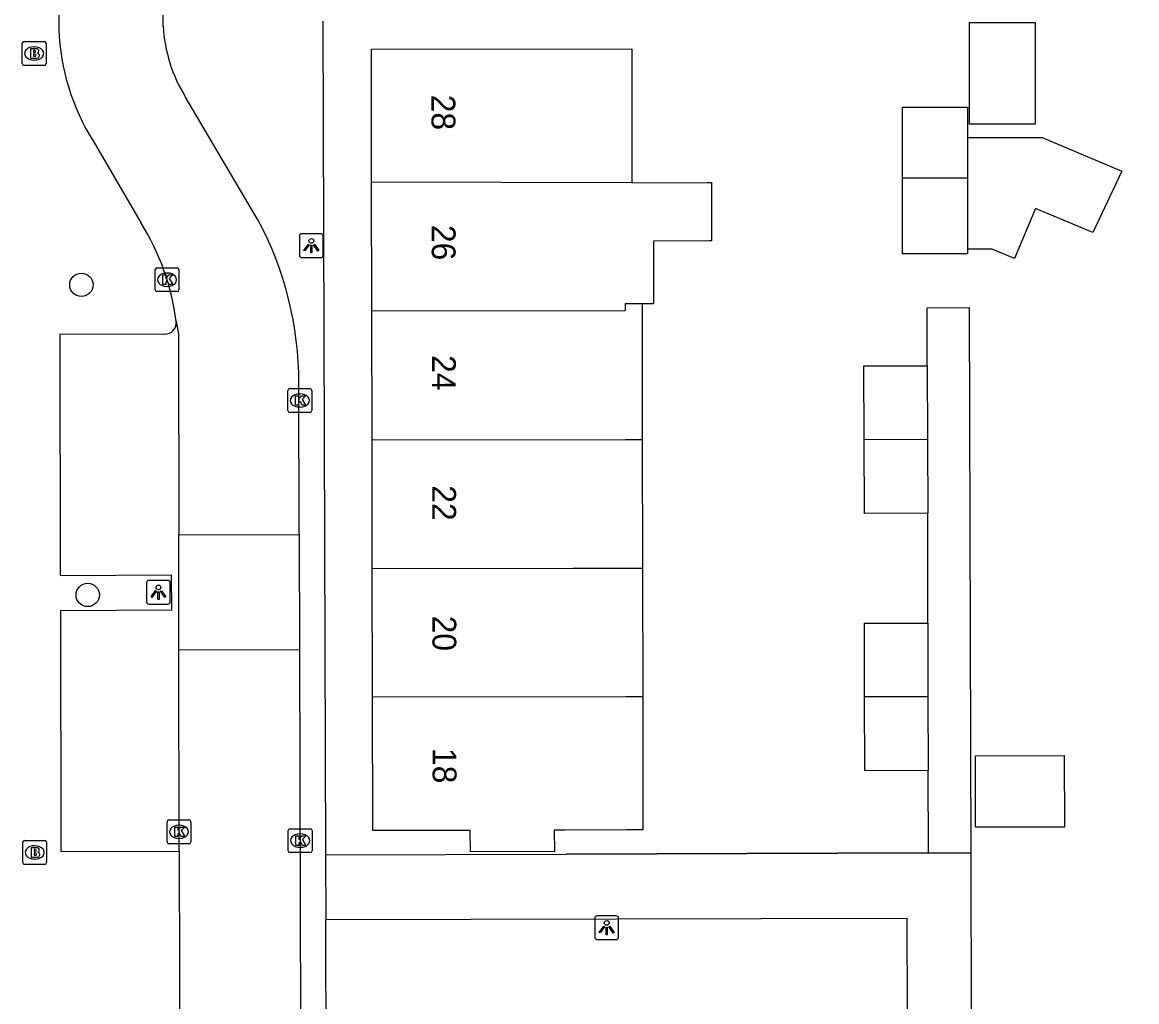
# Model space of a CAD drawing. Extents: x 160457 to 162082, y 388340 to 389736.
# Drawn here: x 160945.33 to 160992.11, y 388549.23 to 388590.34 of the extents above; entities that cross this region are included whole.
import ezdxf

# ---------------------------------------------------------------- set-up
doc = ezdxf.new("R2010")
doc.units = 0
for name, color, linetype in [('IMGEO_Boom', 7, 'Continuous'), ('IMGEO_Brandkraan', 7, 'Continuous'), ('IMGEO_Kolk', 7, 'Continuous'), ('IMGEO_Lichtpunt', 7, 'Continuous'), ('IMGEO_Muur', 7, 'Continuous'), ('IMGEO_Pand', 7, 'Continuous'), ('IMGEO_Pand_nummerreeks', 7, 'Continuous'), ('IMGEO_Rijbaan_lokaal_open', 7, 'Continuous'), ('IMGEO_Voetpad_open', 7, 'Continuous')]:
    doc.layers.add(name, color=color, linetype=linetype)

msp = doc.modelspace()

# ---------------------------------------------------------------- linework, layer by layer
at = {"layer": 'IMGEO_Boom'}
for centre in [(160947.807, 388579.324), (160948.073, 388566.305)]:
    msp.add_circle(centre, 0.489, dxfattribs=at)
at = {"layer": 'IMGEO_Brandkraan'}
for p, q in [((160945.326, 388588.611), (160945.326, 388589.463)), ((160945.401, 388589.537), (160946.253, 388589.537)), ((160945.814, 388589.317), (160945.839, 388589.317)), ((160946.327, 388589.463), (160946.327, 388588.611)), ((160946.253, 388588.537), (160945.401, 388588.537)), ((160945.837, 388588.757), (160945.812, 388588.757)), ((160945.347, 388555.071), (160945.347, 388555.923)), ((160945.422, 388555.997), (160946.274, 388555.997)), ((160945.835, 388555.777), (160945.86, 388555.777)), ((160946.348, 388555.923), (160946.348, 388555.071)), ((160945.858, 388555.217), (160945.833, 388555.217)), ((160946.274, 388554.997), (160945.422, 388554.997))]:
    msp.add_line(p, q, dxfattribs=at)
for points in [[(160945.326, 388588.611), (160945.326, 388589.463)], [(160945.401, 388589.537), (160946.253, 388589.537)], [(160946.327, 388589.463), (160946.327, 388588.611)], [(160945.674, 388589.237), (160945.674, 388588.837), (160945.887, 388588.837)], [(160945.905, 388589.237), (160945.674, 388589.237)], [(160945.853, 388589.156), (160945.799, 388589.156), (160945.799, 388589.08)], [(160945.799, 388589.08), (160945.852, 388589.08)], [(160945.861, 388589.004), (160945.799, 388589.004), (160945.799, 388588.923)], [(160945.799, 388588.923), (160945.861, 388588.923)], [(160946.253, 388588.537), (160945.401, 388588.537)], [(160945.347, 388555.071), (160945.347, 388555.923)], [(160945.422, 388555.997), (160946.274, 388555.997)], [(160945.695, 388555.697), (160945.695, 388555.297), (160945.908, 388555.297)], [(160945.926, 388555.697), (160945.695, 388555.697)], [(160945.874, 388555.616), (160945.82, 388555.616), (160945.82, 388555.54)], [(160946.348, 388555.923), (160946.348, 388555.071)], [(160945.82, 388555.54), (160945.873, 388555.54)], [(160945.882, 388555.464), (160945.82, 388555.464), (160945.82, 388555.383)], [(160945.82, 388555.383), (160945.882, 388555.383)], [(160946.274, 388554.997), (160945.422, 388554.997)]]:
    msp.add_lwpolyline(points, dxfattribs=at)
for centre, radius, start, end in [((160945.403, 388589.461), 0.0765, 91.552, 178.448), ((160945.403, 388589.461), 0.0765, 91.552, 178.448), ((160946.251, 388589.461), 0.0765, 1.552, 88.448), ((160946.251, 388589.461), 0.0765, 1.552, 88.448), ((160945.854, 388589.118), 0.0379, 267.8285, 90.9355), ((160945.862, 388588.963), 0.0404, 269.8759, 90.5077), ((160945.893, 388589.088), 0.251, 268.6676, 293.5347), ((160945.909, 388589.092), 0.145, 59.4692, 91.5367), ((160945.934, 388589.139), 0.0922, 285.5137, 58.1501), ((160945.939, 388588.947), 0.105, 301.3115, 78.989), ((160945.403, 388588.613), 0.0765, 181.552, 268.448), ((160945.403, 388588.613), 0.0765, 181.552, 268.448), ((160946.251, 388588.613), 0.0765, 271.552, 358.448), ((160946.251, 388588.613), 0.0765, 271.552, 358.448), ((160945.424, 388555.921), 0.0765, 91.552, 178.448), ((160945.424, 388555.921), 0.0765, 91.552, 178.448), ((160945.875, 388555.578), 0.0379, 267.8285, 90.9355), ((160945.93, 388555.552), 0.145, 59.4692, 91.5367), ((160945.955, 388555.599), 0.0922, 285.5137, 58.1501), ((160946.272, 388555.921), 0.0765, 1.552, 88.448), ((160946.272, 388555.921), 0.0765, 1.552, 88.448), ((160945.883, 388555.423), 0.0404, 269.8759, 90.5077), ((160945.914, 388555.548), 0.251, 268.6676, 293.5347), ((160945.96, 388555.407), 0.105, 301.3115, 78.989), ((160945.424, 388555.073), 0.0765, 181.552, 268.448), ((160945.424, 388555.073), 0.0765, 181.552, 268.448), ((160946.272, 388555.073), 0.0765, 271.552, 358.448), ((160946.272, 388555.073), 0.0765, 271.552, 358.448)]:
    msp.add_arc(centre, radius, start, end, dxfattribs=at)
for centre, major_axis, ratio, start_param, end_param in [((160945.813, 388589.037), (-0.387, 0.002), 0.722429, 4.712389, 7.853982), ((160945.838, 388589.037), (-0.39, 0.002), 0.717154, 1.570796, 4.712389), ((160945.834, 388555.497), (-0.387, 0.002), 0.722429, 4.712389, 7.853982), ((160945.859, 388555.497), (-0.39, 0.002), 0.717154, 1.570796, 4.712389)]:
    msp.add_ellipse(centre, major_axis=major_axis, ratio=ratio, start_param=start_param, end_param=end_param, dxfattribs=at)
at = {"layer": 'IMGEO_Kolk'}
for p, q in [((160950.903, 388579.112), (160950.903, 388579.964)), ((160950.978, 388580.038), (160951.83, 388580.038)), ((160951.904, 388579.964), (160951.904, 388579.112)), ((160951.391, 388579.818), (160951.416, 388579.818)), ((160951.83, 388579.038), (160950.978, 388579.038)), ((160951.414, 388579.258), (160951.389, 388579.258)), ((160956.477, 388574.042), (160956.477, 388574.894)), ((160956.552, 388574.968), (160957.404, 388574.968)), ((160956.965, 388574.748), (160956.99, 388574.748)), ((160957.478, 388574.894), (160957.478, 388574.042)), ((160957.404, 388573.968), (160956.552, 388573.968)), ((160956.988, 388574.188), (160956.963, 388574.188)), ((160951.406, 388555.936), (160951.406, 388556.788)), ((160951.481, 388556.862), (160952.333, 388556.862)), ((160951.894, 388556.642), (160951.919, 388556.642)), ((160952.407, 388556.788), (160952.407, 388555.936)), ((160951.917, 388556.082), (160951.892, 388556.082)), ((160956.491, 388555.567), (160956.491, 388556.419)), ((160956.566, 388556.493), (160957.418, 388556.493)), ((160956.979, 388556.273), (160957.004, 388556.273)), ((160957.492, 388556.419), (160957.492, 388555.567)), ((160952.333, 388555.862), (160951.481, 388555.862)), ((160957.002, 388555.713), (160956.977, 388555.713)), ((160957.418, 388555.493), (160956.566, 388555.493))]:
    msp.add_line(p, q, dxfattribs=at)
for points in [[(160950.903, 388579.112), (160950.903, 388579.964)], [(160950.978, 388580.038), (160951.83, 388580.038)], [(160951.904, 388579.964), (160951.904, 388579.112)], [(160951.224, 388579.738), (160951.347, 388579.738), (160951.347, 388579.587), (160951.477, 388579.738), (160951.641, 388579.738), (160951.495, 388579.587), (160951.648, 388579.338), (160951.496, 388579.338), (160951.411, 388579.502), (160951.347, 388579.435), (160951.347, 388579.338), (160951.224, 388579.338), (160951.224, 388579.738)], [(160951.83, 388579.038), (160950.978, 388579.038)], [(160956.477, 388574.042), (160956.477, 388574.894)], [(160956.552, 388574.968), (160957.404, 388574.968)], [(160957.478, 388574.894), (160957.478, 388574.042)], [(160956.798, 388574.668), (160956.921, 388574.668), (160956.921, 388574.517), (160957.051, 388574.668), (160957.215, 388574.668), (160957.069, 388574.517), (160957.222, 388574.268), (160957.07, 388574.268), (160956.985, 388574.432), (160956.921, 388574.365), (160956.921, 388574.268), (160956.798, 388574.268), (160956.798, 388574.668)], [(160957.404, 388573.968), (160956.552, 388573.968)], [(160951.406, 388555.936), (160951.406, 388556.788)], [(160951.481, 388556.862), (160952.333, 388556.862)], [(160951.727, 388556.562), (160951.85, 388556.562), (160951.85, 388556.411), (160951.98, 388556.562), (160952.144, 388556.562), (160951.998, 388556.411), (160952.151, 388556.162), (160951.999, 388556.162), (160951.914, 388556.326), (160951.85, 388556.259), (160951.85, 388556.162), (160951.727, 388556.162), (160951.727, 388556.562)], [(160952.407, 388556.788), (160952.407, 388555.936)], [(160956.491, 388555.567), (160956.491, 388556.419)], [(160956.566, 388556.493), (160957.418, 388556.493)], [(160956.812, 388556.193), (160956.935, 388556.193), (160956.935, 388556.042), (160957.065, 388556.193), (160957.229, 388556.193), (160957.083, 388556.042), (160957.236, 388555.793), (160957.084, 388555.793), (160956.999, 388555.957), (160956.935, 388555.89), (160956.935, 388555.793), (160956.812, 388555.793), (160956.812, 388556.193)], [(160957.492, 388556.419), (160957.492, 388555.567)], [(160952.333, 388555.862), (160951.481, 388555.862)], [(160957.418, 388555.493), (160956.566, 388555.493)]]:
    msp.add_lwpolyline(points, dxfattribs=at)
for centre, start, end in [((160950.98, 388579.962), 91.552, 178.448), ((160950.98, 388579.962), 91.552, 178.448), ((160951.828, 388579.962), 1.552, 88.448), ((160951.828, 388579.962), 1.552, 88.448), ((160950.98, 388579.114), 181.552, 268.448), ((160950.98, 388579.114), 181.552, 268.448), ((160951.828, 388579.114), 271.552, 358.448), ((160951.828, 388579.114), 271.552, 358.448), ((160956.554, 388574.892), 91.552, 178.448), ((160956.554, 388574.892), 91.552, 178.448), ((160957.402, 388574.892), 1.552, 88.448), ((160957.402, 388574.892), 1.552, 88.448), ((160956.554, 388574.044), 181.552, 268.448), ((160956.554, 388574.044), 181.552, 268.448), ((160957.402, 388574.044), 271.552, 358.448), ((160957.402, 388574.044), 271.552, 358.448), ((160951.483, 388556.786), 91.552, 178.448), ((160951.483, 388556.786), 91.552, 178.448), ((160952.331, 388556.786), 1.552, 88.448), ((160952.331, 388556.786), 1.552, 88.448), ((160956.568, 388556.417), 91.552, 178.448), ((160956.568, 388556.417), 91.552, 178.448), ((160957.416, 388556.417), 1.552, 88.448), ((160957.416, 388556.417), 1.552, 88.448), ((160951.483, 388555.938), 181.552, 268.448), ((160951.483, 388555.938), 181.552, 268.448), ((160952.331, 388555.938), 271.552, 358.448), ((160952.331, 388555.938), 271.552, 358.448), ((160956.568, 388555.569), 181.552, 268.448), ((160956.568, 388555.569), 181.552, 268.448), ((160957.416, 388555.569), 271.552, 358.448), ((160957.416, 388555.569), 271.552, 358.448)]:
    msp.add_arc(centre, 0.0765, start, end, dxfattribs=at)
for centre, major_axis, ratio, start_param, end_param in [((160951.39, 388579.538), (-0.387, 0.002), 0.722429, 4.712389, 7.853982), ((160951.415, 388579.538), (-0.39, 0.002), 0.717154, 1.570796, 4.712389), ((160956.964, 388574.468), (-0.387, 0.002), 0.722429, 4.712389, 7.853982), ((160956.989, 388574.468), (-0.39, 0.002), 0.717154, 1.570796, 4.712389), ((160951.893, 388556.362), (-0.387, 0.002), 0.722429, 4.712389, 7.853982), ((160951.918, 388556.362), (-0.39, 0.002), 0.717154, 1.570796, 4.712389), ((160956.978, 388555.993), (-0.387, 0.002), 0.722429, 4.712389, 7.853982), ((160957.003, 388555.993), (-0.39, 0.002), 0.717154, 1.570796, 4.712389)]:
    msp.add_ellipse(centre, major_axis=major_axis, ratio=ratio, start_param=start_param, end_param=end_param, dxfattribs=at)
at = {"layer": 'IMGEO_Lichtpunt'}
for p, q in [((160956.963, 388581.371), (160956.963, 388580.564)), ((160956.963, 388581.371), (160956.963, 388580.564)), ((160957.865, 388581.466), (160957.057, 388581.466)), ((160957.865, 388581.466), (160957.057, 388581.466)), ((160957.959, 388580.564), (160957.959, 388581.371)), ((160957.959, 388580.564), (160957.959, 388581.371)), ((160957.057, 388580.47), (160957.865, 388580.47)), ((160957.057, 388580.47), (160957.865, 388580.47)), ((160950.543, 388566.822), (160950.543, 388566.015)), ((160950.543, 388566.822), (160950.543, 388566.015)), ((160951.445, 388566.917), (160950.637, 388566.917)), ((160951.445, 388566.917), (160950.637, 388566.917)), ((160951.539, 388566.015), (160951.539, 388566.822)), ((160951.539, 388566.015), (160951.539, 388566.822)), ((160950.637, 388565.921), (160951.445, 388565.921)), ((160950.637, 388565.921), (160951.445, 388565.921)), ((160970.263, 388552.836), (160969.455, 388552.836)), ((160970.263, 388552.836), (160969.455, 388552.836)), ((160969.361, 388552.741), (160969.361, 388551.934)), ((160969.361, 388552.741), (160969.361, 388551.934)), ((160970.357, 388551.934), (160970.357, 388552.741)), ((160970.357, 388551.934), (160970.357, 388552.741)), ((160969.455, 388551.84), (160970.263, 388551.84)), ((160969.455, 388551.84), (160970.263, 388551.84))]:
    msp.add_line(p, q, dxfattribs=at)
for points in [[(160957.337, 388581.035), (160957.376, 388581.007), (160957.188, 388580.745), (160957.15, 388580.772), (160957.337, 388581.035)], [(160957.439, 388580.987), (160957.486, 388580.987), (160957.486, 388580.665), (160957.439, 388580.665), (160957.439, 388580.987)], [(160957.549, 388581.007), (160957.587, 388581.034), (160957.774, 388580.772), (160957.735, 388580.744), (160957.549, 388581.007)], [(160950.917, 388566.486), (160950.956, 388566.458), (160950.768, 388566.196), (160950.73, 388566.223), (160950.917, 388566.486)], [(160951.019, 388566.438), (160951.066, 388566.438), (160951.066, 388566.116), (160951.019, 388566.116), (160951.019, 388566.438)], [(160951.129, 388566.458), (160951.167, 388566.485), (160951.354, 388566.223), (160951.315, 388566.195), (160951.129, 388566.458)], [(160969.735, 388552.405), (160969.774, 388552.377), (160969.586, 388552.115), (160969.548, 388552.142), (160969.735, 388552.405)], [(160969.837, 388552.357), (160969.884, 388552.357), (160969.884, 388552.035), (160969.837, 388552.035), (160969.837, 388552.357)], [(160969.947, 388552.377), (160969.985, 388552.404), (160970.172, 388552.142), (160970.133, 388552.114), (160969.947, 388552.377)]]:
    msp.add_lwpolyline(points, dxfattribs=at)
for centre in [(160957.462, 388581.169), (160951.042, 388566.62), (160969.86, 388552.539)]:
    msp.add_circle(centre, 0.0994, dxfattribs=at)
for centre, start, end in [((160957.057, 388581.371), 90, 180), ((160957.057, 388581.371), 90, 180), ((160957.865, 388581.371), 0, 90), ((160957.865, 388581.371), 0, 90), ((160957.057, 388580.564), 180, 270), ((160957.057, 388580.564), 180, 270), ((160957.865, 388580.564), 270, 0), ((160957.865, 388580.564), 270, 360), ((160950.637, 388566.822), 90, 180), ((160950.637, 388566.822), 90, 180), ((160951.445, 388566.822), 0, 90), ((160951.445, 388566.822), 0, 90), ((160950.637, 388566.015), 180, 270), ((160950.637, 388566.015), 180, 270), ((160951.445, 388566.015), 270, 0), ((160951.445, 388566.015), 270, 360), ((160969.455, 388552.741), 90, 180), ((160969.455, 388552.741), 90, 180), ((160970.263, 388552.741), 0, 90), ((160970.263, 388552.741), 0, 90), ((160969.455, 388551.934), 180, 270), ((160969.455, 388551.934), 180, 270), ((160970.263, 388551.934), 270, 0), ((160970.263, 388551.934), 270, 360)]:
    msp.add_arc(centre, 0.0946, start, end, dxfattribs=at)
at = {"layer": 'IMGEO_Muur'}
for points in [[(160983.369, 388555.475), (160968.14, 388555.428)], [(160985.147, 388555.481), (160985.162, 388548.37), (161001.342, 388548.405)]]:
    msp.add_lwpolyline(points, dxfattribs=at)
at = {"layer": 'IMGEO_Pand'}
for points in [[(160987.85, 388586.062), (160985.087, 388586.062), (160985.087, 388590.342), (160987.85, 388590.342), (160987.85, 388586.062)], [(160959.991, 388583.627), (160959.981, 388589.211), (160970.911, 388589.231), (160970.921, 388583.612)], [(160982.273, 388583.801), (160982.273, 388586.785), (160985.003, 388586.785), (160985.003, 388585.504)], [(160985.003, 388585.504), (160985.003, 388583.806)], [(160985.003, 388585.504), (160988.141, 388585.504), (160991.484, 388584.1), (160990.267, 388581.523), (160987.857, 388582.534), (160986.975, 388580.433), (160986.04, 388580.825), (160985.003, 388580.825)], [(160985.003, 388583.806), (160982.502, 388583.805), (160982.273, 388583.801)], [(160985.003, 388580.825), (160985.003, 388580.627), (160982.273, 388580.627), (160982.273, 388583.801)], [(160985.003, 388583.806), (160985.003, 388580.825)], [(160970.921, 388583.612), (160959.991, 388583.627)], [(160960, 388578.222), (160959.991, 388583.627)], [(160970.921, 388583.612), (160974.072, 388583.618), (160974.253, 388583.618), (160974.256, 388581.167), (160974.175, 388581.167), (160971.823, 388581.163), (160971.83, 388578.532), (160971.583, 388578.531), (160971.342, 388578.53)], [(160971.342, 388578.53), (160970.636, 388578.528), (160970.636, 388578.23), (160960, 388578.222)], [(160971.342, 388578.53), (160971.352, 388572.83)], [(160960.01, 388572.822), (160960, 388578.222)], [(160980.669, 388572.838), (160980.66, 388575.917), (160983.318, 388575.926)], [(160983.318, 388575.926), (160983.328, 388572.84)], [(160960.01, 388572.822), (160970.646, 388572.83), (160971.352, 388572.83)], [(160960.02, 388567.422), (160960.01, 388572.822)], [(160971.352, 388572.83), (160971.362, 388567.433)], [(160980.669, 388572.838), (160983.328, 388572.84)], [(160983.338, 388569.735), (160980.679, 388569.727), (160980.669, 388572.838)], [(160983.328, 388572.84), (160983.338, 388569.735)], [(160960.02, 388567.422), (160968.434, 388567.428), (160970.656, 388567.432), (160971.362, 388567.433)], [(160960.029, 388562.021), (160960.02, 388567.422)], [(160971.362, 388567.433), (160971.372, 388562.031)], [(160980.689, 388562.038), (160980.68, 388565.117), (160983.338, 388565.126)], [(160983.338, 388565.126), (160983.348, 388562.041)], [(160971.372, 388562.031), (160970.666, 388562.03), (160960.029, 388562.021)], [(160971.372, 388562.031), (160971.382, 388556.442), (160970.676, 388556.44), (160968.137, 388556.434), (160967.655, 388556.433), (160967.667, 388555.533), (160964.137, 388555.524), (160964.125, 388556.423), (160960.039, 388556.412), (160960.029, 388562.021)], [(160980.689, 388562.038), (160983.348, 388562.041)], [(160983.358, 388558.935), (160980.699, 388558.927), (160980.689, 388562.038)], [(160983.348, 388562.041), (160983.358, 388558.935)], [(160989.066, 388559.56), (160989.073, 388556.559), (160985.348, 388556.551), (160985.341, 388559.551), (160989.066, 388559.56)]]:
    msp.add_lwpolyline(points, dxfattribs=at)
at = {"layer": 'IMGEO_Rijbaan_lokaal_open'}
for points in [[(160946.624, 388615.788), (160946.807, 388609.308), (160946.861, 388593.811), (160946.863, 388590.044)], [(160951.241, 388590.183), (160951.242, 388590.402), (160951.224, 388593.835), (160951.194, 388615.777)], [(160955.213, 388582.054), (160952.174, 388587.207)], [(160948.296, 388585.366), (160950.322, 388581.918)], [(160951.791, 388577.788), (160951.887, 388577.271), (160951.897, 388568.831)], [(160956.954, 388568.844), (160956.936, 388575.196)], [(160951.897, 388568.831), (160956.954, 388568.844)], [(160951.904, 388563.991), (160951.897, 388568.831)], [(160956.954, 388568.844), (160956.967, 388564.004)], [(160956.967, 388564.004), (160951.904, 388563.991)], [(160951.914, 388555.541), (160951.904, 388563.991)], [(160956.967, 388564.004), (160957.054, 388532.505), (160957.055, 388529.559)], [(160951.914, 388555.541), (160951.929, 388550.409), (160951.946, 388543.023), (160951.914, 388537.902)]]:
    msp.add_lwpolyline(points, dxfattribs=at)
for centre, radius, start, end in [((160956.377, 388590.4), 9.521, 182.1429, 211.9196), ((160957.555, 388590.528), 6.323, 183.1288, 211.6844), ((160941.357, 388576.403), 10.525, 7.561, 31.5989), ((160942.632, 388575.248), 14.304, 359.7926, 28.4136)]:
    msp.add_arc(centre, radius, start, end, dxfattribs=at)
at = {"layer": 'IMGEO_Voetpad_open'}
for points in [[(160957.949, 388590.391), (160958.051, 388555.395)], [(160983.318, 388575.926), (160983.31, 388578.36), (160985.07, 388578.366), (160985.147, 388555.481)], [(160951.302, 388577.252), (160946.905, 388577.232), (160946.922, 388567.128), (160951.574, 388567.157), (160951.585, 388565.673), (160946.926, 388565.636), (160946.95, 388555.547), (160951.914, 388555.541)], [(160983.338, 388565.126), (160983.338, 388569.735)], [(160983.369, 388555.475), (160983.358, 388558.935)], [(160958.051, 388555.395), (160968.14, 388555.428), (160983.369, 388555.475)], [(160958.051, 388555.395), (160958.068, 388552.684)], [(160983.369, 388555.475), (160985.147, 388555.481)], [(160985.147, 388555.481), (160985.162, 388548.37)], [(160958.068, 388552.684), (160982.455, 388552.733), (160982.501, 388540.818), (160958.098, 388540.667)], [(160958.098, 388540.667), (160958.068, 388552.684)]]:
    msp.add_lwpolyline(points, dxfattribs=at)
msp.add_arc((160951.309, 388577.737), 0.485, 269.1937, 6.057, dxfattribs=at)

# ---------------------------------------------------------------- texts
at = {"layer": 'IMGEO_Pand_nummerreeks'}
for s, rotation, p in [('28', 270.1013, (160962.504, 388587.305)), ('26', 270.1029, (160962.514, 388581.841)), ('24', 270.1029, (160962.524, 388576.375)), ('22', 270.1029, (160962.534, 388570.911)), ('20', 270.1029, (160962.543, 388565.439)), ('18', 270.1029, (160962.553, 388559.881))]:
    msp.add_text(s, height=1, rotation=rotation, dxfattribs=at).set_placement(p)

doc.saveas('drawing.dxf')
